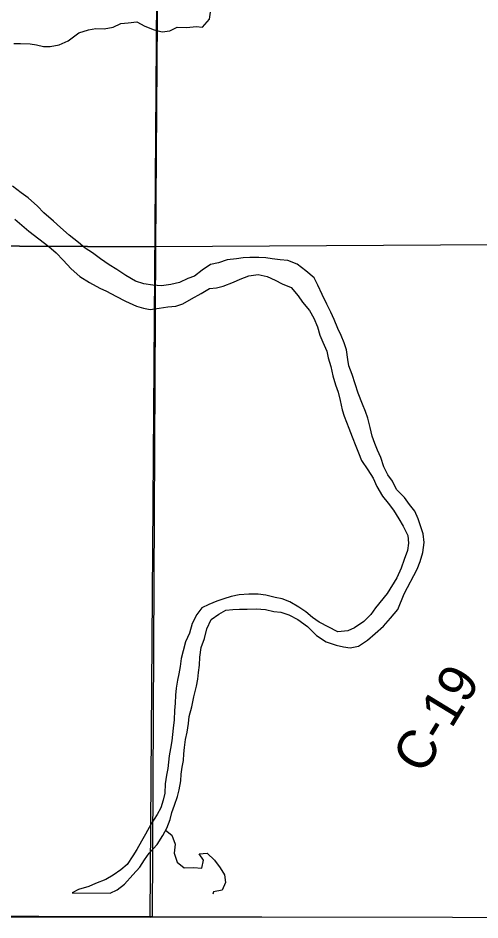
# Model space of a CAD drawing. Extents: x 1772825 to 1773716, y 1138558 to 1139032.
# Drawn here: x 1772827.863 to 1772828.204, y 1138558.123 to 1138558.79 of the extents above; entities that cross this region are included whole.
import ezdxf

# ---------------------------------------------------------------- set-up
doc = ezdxf.new("R2010")
doc.units = 0
for name, color, linetype in [('GM_X_County_Road_Text', 7, 'Continuous'), ('GM_X_Major_River', 7, 'Continuous'), ('GM_X_Minor_River', 7, 'Continuous'), ('GM_X_Section', 7, 'Continuous'), ('GM_X_Township', 7, 'Continuous')]:
    doc.layers.add(name, color=color, linetype=linetype)

msp = doc.modelspace()

# ---------------------------------------------------------------- linework, layer by layer
at = {"layer": 'GM_X_Major_River'}
msp.add_line((1772827.90259, 1138558.14267), (1772827.93063, 1138558.1424), dxfattribs=at)
for points in [[(1772827.88872, 1138558.63969), (1772827.88174, 1138558.64582), (1772827.87703, 1138558.65079), (1772827.87006, 1138558.6571), (1772827.86477, 1138558.66075), (1772827.85854, 1138558.66554)], [(1772827.86008, 1138558.64124), (1772827.86535, 1138558.63665), (1772827.87045, 1138558.63243), (1772827.87799, 1138558.62668), (1772827.88535, 1138558.62094), (1772827.89082, 1138558.61634), (1772827.8959, 1138558.6108), (1772827.90174, 1138558.6045), (1772827.90815, 1138558.59876), (1772827.91533, 1138558.59434), (1772827.92308, 1138558.5901), (1772827.92799, 1138558.58779), (1772827.93499, 1138558.58432), (1772827.94198, 1138558.58047), (1772827.95011, 1138558.57681), (1772827.95522, 1138558.57525), (1772827.96015, 1138558.57445), (1772827.96699, 1138558.57535), (1772827.97344, 1138558.57625), (1772827.97933, 1138558.57678), (1772827.98446, 1138558.57844), (1772827.99094, 1138558.58219), (1772827.99799, 1138558.58612), (1772828.00409, 1138558.58987), (1772828.00922, 1138558.5904), (1772828.01416, 1138558.5915), (1772828.02196, 1138558.59448), (1772828.02672, 1138558.59672), (1772828.03319, 1138558.59914), (1772828.04021, 1138558.60022), (1772828.04666, 1138558.59884), (1772828.05271, 1138558.59614), (1772828.05781, 1138558.59326), (1772828.06443, 1138558.59055), (1772828.0697, 1138558.58444), (1772828.07289, 1138558.57967), (1772828.07797, 1138558.57356), (1772828.08115, 1138558.56803), (1772828.08395, 1138558.56156), (1772828.08561, 1138558.55529), (1772828.08785, 1138558.55015), (1772828.09084, 1138558.54349), (1772828.09194, 1138558.53854), (1772828.09379, 1138558.53208), (1772828.09526, 1138558.52524), (1772828.0973, 1138558.51858), (1772828.09916, 1138558.51326), (1772828.10063, 1138558.50698), (1772828.10229, 1138558.50014), (1772828.10377, 1138558.49539), (1772828.10713, 1138558.48663), (1772828.10954, 1138558.48016), (1772828.11234, 1138558.47312), (1772828.11439, 1138558.46836), (1772828.11644, 1138558.46266), (1772828.12113, 1138558.4556), (1772828.12507, 1138558.4495), (1772828.12787, 1138558.44341), (1772828.13199, 1138558.43617), (1772828.13632, 1138558.43101), (1772828.14027, 1138558.42586), (1772828.14401, 1138558.41938), (1772828.14739, 1138558.41404), (1772828.15075, 1138558.40699), (1772828.15128, 1138558.4013), (1772828.15048, 1138558.39599), (1772828.14797, 1138558.38937), (1772828.14584, 1138558.38294), (1772828.14275, 1138558.37575), (1772828.1354, 1138558.36408)], [(1772828.14802, 1138558.36398), (1772828.15778, 1138558.38209), (1772828.15991, 1138558.38795), (1772828.16186, 1138558.39458), (1772828.16286, 1138558.40178), (1772828.16215, 1138558.40843), (1772828.1601, 1138558.41432), (1772828.15843, 1138558.41946), (1772828.15582, 1138558.42498), (1772828.15206, 1138558.43013), (1772828.1483, 1138558.43509), (1772828.14227, 1138558.44102), (1772828.13947, 1138558.4473), (1772828.1359, 1138558.45207), (1772828.13291, 1138558.45779), (1772828.13087, 1138558.46482), (1772828.12826, 1138558.47035), (1772828.12639, 1138558.4751), (1772828.12435, 1138558.48062), (1772828.12288, 1138558.48708), (1772828.12122, 1138558.49393), (1772828.11955, 1138558.49887), (1772828.11731, 1138558.50439), (1772828.11395, 1138558.51238), (1772828.11192, 1138558.51923), (1772828.1095, 1138558.52627), (1772828.10708, 1138558.53255), (1772828.10635, 1138558.5373), (1772828.10546, 1138558.54451), (1772828.10379, 1138558.54965), (1772828.10155, 1138558.55498), (1772828.09893, 1138558.56031), (1772828.09632, 1138558.56697), (1772828.0939, 1138558.5723), (1772828.0909, 1138558.5784), (1772828.08754, 1138558.58544), (1772828.08418, 1138558.5923), (1772828.08156, 1138558.59782), (1772828.07534, 1138558.60299), (1772828.06892, 1138558.60778), (1772828.06211, 1138558.61049), (1772828.05642, 1138558.6111), (1772828.05054, 1138558.61172), (1772828.04581, 1138558.61251), (1772828.04068, 1138558.61274), (1772828.03385, 1138558.61279), (1772828.02892, 1138558.61264), (1772828.02398, 1138558.61192), (1772828.01715, 1138558.61121), (1772828.01068, 1138558.60898), (1772828.00479, 1138558.6077), (1772827.99869, 1138558.60357), (1772827.99296, 1138558.59906), (1772827.98802, 1138558.5972), (1772827.98192, 1138558.59421), (1772827.97546, 1138558.59274), (1772827.96862, 1138558.59185), (1772827.96218, 1138558.59228), (1772827.95554, 1138558.59327), (1772827.94948, 1138558.59522), (1772827.94231, 1138558.59945), (1772827.93551, 1138558.60405), (1772827.93003, 1138558.60751), (1772827.92342, 1138558.61192), (1772827.91757, 1138558.61633), (1772827.91229, 1138558.61978), (1772827.90719, 1138558.624), (1772827.9004, 1138558.62936), (1772827.89399, 1138558.63491), (1772827.88872, 1138558.63969)], [(1772828.03332, 1138558.36376), (1772828.02611, 1138558.36306), (1772828.02003, 1138558.36198), (1772828.0147, 1138558.36012), (1772828.00957, 1138558.35846), (1772828.00367, 1138558.35604), (1772827.99834, 1138558.35361), (1772827.99488, 1138558.34871), (1772827.99141, 1138558.3419), (1772827.98945, 1138558.33489), (1772827.98636, 1138558.32846), (1772827.9846, 1138558.32184), (1772827.98322, 1138558.31596), (1772827.98241, 1138558.31008), (1772827.98142, 1138558.30478), (1772827.98043, 1138558.30004), (1772827.97943, 1138558.29416), (1772827.97901, 1138558.28904), (1772827.97876, 1138558.28297), (1772827.97815, 1138558.27747), (1772827.9779, 1138558.27064), (1772827.97728, 1138558.26457), (1772827.97686, 1138558.25983), (1772827.97625, 1138558.25509), (1772827.97525, 1138558.2494), (1772827.97426, 1138558.24409), (1772827.97384, 1138558.23935), (1772827.97342, 1138558.23461), (1772827.97243, 1138558.22968), (1772827.97143, 1138558.22342), (1772827.97099, 1138558.2164), (1772827.9698, 1138558.2111), (1772827.96805, 1138558.20542), (1772827.96554, 1138558.2005), (1772827.96112, 1138558.19371), (1772827.95669, 1138558.18615), (1772827.9538, 1138558.18086), (1772827.95034, 1138558.17481), (1772827.94745, 1138558.1699), (1772827.94322, 1138558.16367), (1772827.93845, 1138558.15954), (1772827.93291, 1138558.1556), (1772827.92757, 1138558.1526), (1772827.91977, 1138558.14944), (1772827.91482, 1138558.14739), (1772827.90722, 1138558.14499), (1772827.90259, 1138558.14267)], [(1772828.1354, 1138558.36408), (1772828.12674, 1138558.3535), (1772828.12347, 1138558.34859), (1772828.11812, 1138558.34332), (1772828.11125, 1138558.33863), (1772828.1063, 1138558.33658), (1772828.09909, 1138558.33588), (1772828.08511, 1138558.34302), (1772828.08021, 1138558.34648), (1772828.07532, 1138558.3507), (1772828.07022, 1138558.35397), (1772828.06362, 1138558.35801), (1772828.05795, 1138558.36014), (1772828.05265, 1138558.36113), (1772828.04583, 1138558.3629), (1772828.04015, 1138558.36371), (1772828.03332, 1138558.36376)], [(1772828.03873, 1138558.35271), (1772828.04555, 1138558.35227), (1772828.0518, 1138558.35089), (1772828.05692, 1138558.35028), (1772828.06278, 1138558.34833), (1772828.06939, 1138558.34486), (1772828.07655, 1138558.33968), (1772828.08332, 1138558.33317), (1772828.09049, 1138558.32836), (1772828.09768, 1138558.32602), (1772828.10316, 1138558.32465), (1772828.10809, 1138558.32385), (1772828.11436, 1138558.32513), (1772828.12104, 1138558.32963), (1772828.12658, 1138558.33452), (1772828.13288, 1138558.33997), (1772828.13787, 1138558.346), (1772828.14342, 1138558.35241), (1772828.14802, 1138558.36398)], [(1772827.93063, 1138558.1424), (1772827.93585, 1138558.14494), (1772827.9412, 1138558.14907), (1772827.94733, 1138558.15586), (1772827.95269, 1138558.1617), (1772827.95596, 1138558.16698), (1772827.95961, 1138558.17208), (1772827.96535, 1138558.1783), (1772827.96958, 1138558.1851), (1772827.97247, 1138558.19039), (1772827.97499, 1138558.19701), (1772827.97618, 1138558.20212), (1772827.97831, 1138558.20761), (1772827.98045, 1138558.21386), (1772827.98163, 1138558.21897), (1772827.98301, 1138558.22561), (1772827.98325, 1138558.23054), (1772827.98386, 1138558.23566), (1772827.98485, 1138558.24059), (1772827.98527, 1138558.24552), (1772827.98569, 1138558.25026), (1772827.9865, 1138558.25614), (1772827.98768, 1138558.26144), (1772827.9885, 1138558.26789), (1772827.98911, 1138558.2732), (1772827.99107, 1138558.2804), (1772827.99246, 1138558.28779), (1772827.99461, 1138558.29556), (1772827.99542, 1138558.30067), (1772827.99603, 1138558.30579), (1772827.99664, 1138558.31111), (1772827.99707, 1138558.31699), (1772827.99808, 1138558.32419), (1772828.00042, 1138558.33082), (1772828.00219, 1138558.33802), (1772828.00547, 1138558.34482), (1772828.011, 1138558.34876), (1772828.01615, 1138558.35176), (1772828.02128, 1138558.35228), (1772828.02621, 1138558.35262), (1772828.03209, 1138558.35257), (1772828.03873, 1138558.35271)]]:
    msp.add_lwpolyline(points, dxfattribs=at)
at = {"layer": 'GM_X_Minor_River'}
for points in [[(1772827.8595, 1138558.77121), (1772827.86443, 1138558.77117), (1772827.87145, 1138558.77093), (1772827.87619, 1138558.77032), (1772827.88149, 1138558.76896), (1772827.88643, 1138558.76892), (1772827.89308, 1138558.7702), (1772827.89955, 1138558.77318), (1772827.90756, 1138558.77919), (1772827.9146, 1138558.78142), (1772827.92011, 1138558.78233), (1772827.92637, 1138558.78209), (1772827.93302, 1138558.78337), (1772827.93854, 1138558.78598), (1772827.94404, 1138558.78651), (1772827.9505, 1138558.78722), (1772827.95636, 1138558.78414), (1772827.96317, 1138558.78124), (1772827.96904, 1138558.77987), (1772827.97474, 1138558.78058), (1772827.98026, 1138558.7832), (1772827.98728, 1138558.78314), (1772827.9943, 1138558.78366), (1772827.99904, 1138558.78324), (1772828.00402, 1138558.78909), (1772828.00482, 1138558.7944)], [(1772827.97165, 1138558.18889), (1772827.97622, 1138558.18523), (1772827.97863, 1138558.17876), (1772827.978, 1138558.17193), (1772827.98022, 1138558.16526), (1772827.9855, 1138558.16123), (1772827.99233, 1138558.16137), (1772827.99839, 1138558.16094), (1772827.99958, 1138558.16681), (1772827.9964, 1138558.17158), (1772828.00247, 1138558.1721), (1772828.00774, 1138558.16674), (1772828.01205, 1138558.16101), (1772828.01523, 1138558.15605), (1772828.01594, 1138558.15035), (1772828.01343, 1138558.14468), (1772828.00716, 1138558.1434), (1772828.00656, 1138558.14166)]]:
    msp.add_lwpolyline(points, dxfattribs=at)
at = {"layer": 'GM_X_Section'}
for points in [[(1772827.96782, 1138559.12738), (1772827.96416, 1138558.62078), (1772827.46154, 1138558.62309), (1772827.46569, 1138559.12001)], [(1772827.96782, 1138559.12738), (1772827.96764, 1138559.12908), (1772828.47764, 1138559.12426), (1772828.47004, 1138558.62357), (1772827.96416, 1138558.62078)], [(1772827.96416, 1138558.62078), (1772827.96178, 1138558.12481), (1772827.45878, 1138558.12628), (1772827.46154, 1138558.62309)]]:
    msp.add_lwpolyline(points, close=True, dxfattribs=at)
at = {"layer": 'GM_X_Township'}
for points in [[(1772826.38448, 1138558.12698), (1772826.95724, 1138558.12615), (1772827.5595, 1138558.12526), (1772827.58566, 1138558.12522), (1772827.9602, 1138558.12465), (1772827.96578, 1138558.87412), (1772827.96954, 1138559.37836), (1772827.97328, 1138559.62742), (1772827.97337, 1138559.80486), (1772827.97201, 1138559.91528), (1772827.97425, 1138560.12644), (1772827.9761, 1138560.40209), (1772827.97721, 1138560.57985), (1772827.98261, 1138561.13548), (1772827.5133, 1138561.13112), (1772827.29755, 1138561.12774), (1772826.84422, 1138561.12674)], [(1772829.35677, 1138558.12255), (1772828.65972, 1138558.1236), (1772828.46538, 1138558.12388), (1772828.04276, 1138558.12453), (1772827.9602, 1138558.12465), (1772827.96578, 1138558.87412), (1772827.96954, 1138559.37836), (1772827.97328, 1138559.62742), (1772827.97337, 1138559.80486), (1772827.97201, 1138559.91528), (1772827.97425, 1138560.12644), (1772827.9761, 1138560.40209), (1772827.97721, 1138560.57985), (1772827.98261, 1138561.13548), (1772828.37391, 1138561.13581), (1772828.73894, 1138561.13584), (1772828.93513, 1138561.13617), (1772829.26496, 1138561.13428)]]:
    msp.add_lwpolyline(points, dxfattribs=at)

# ---------------------------------------------------------------- texts
at = {"layer": 'GM_X_County_Road_Text'}
msp.add_text('C-19', height=0.028409, rotation=58.63507, dxfattribs=at).set_placement((1772828.16217, 1138558.2293))

doc.saveas('drawing.dxf')
